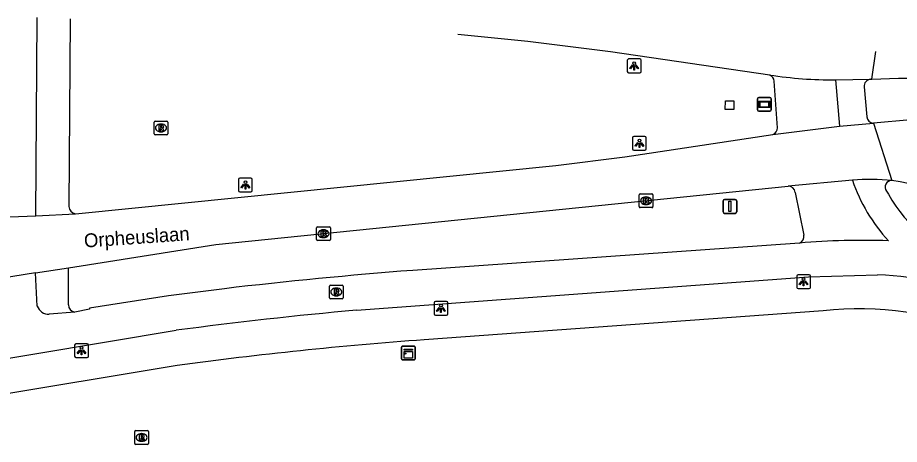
# Model space of a CAD drawing. Extents: x 161761 to 162722, y 384793 to 385405.
# Drawn here: x 161913.2 to 161977.1, y 385354.7 to 385385.6 of the extents above; entities that cross this region are included whole.
import ezdxf

# ---------------------------------------------------------------- set-up
doc = ezdxf.new("R2010")
doc.units = 0
for name, color, linetype in [('IMGEO_Berm_groen', 7, 'Continuous'), ('IMGEO_Fietspad_gesloten', 7, 'Continuous'), ('IMGEO_Kast', 7, 'Continuous'), ('IMGEO_Kolk', 7, 'Continuous'), ('IMGEO_Lichtpunt', 7, 'Continuous'), ('IMGEO_Openbare_ruimte_label', 7, 'Continuous'), ('IMGEO_Rijbaan_lokaal_gesloten', 7, 'Continuous'), ('IMGEO_Rioolput', 7, 'Continuous'), ('IMGEO_Straatnaambord', 7, 'Continuous'), ('IMGEO_Verkeersbordpaal', 7, 'Continuous'), ('IMGEO_Voetpad_open', 7, 'Continuous')]:
    doc.layers.add(name, color=color, linetype=linetype)

msp = doc.modelspace()

# ---------------------------------------------------------------- linework, layer by layer
at = {"layer": 'IMGEO_Berm_groen'}
msp.add_lwpolyline([(161964.504, 385379.586), (161965.1, 385379.595), (161965.105, 385378.974), (161964.466, 385378.952), (161964.504, 385379.586)], dxfattribs=at)
at = {"layer": 'IMGEO_Fietspad_gesloten'}
for points in [[(161914.544, 385371.27), (161914.64, 385385.619)], [(161972.454, 385381.101), (161972.759, 385377.761)], [(161974.546, 385380.611), (161974.742, 385378.438)], [(161976.151, 385373.042), (161976.299, 385372.83)], [(161969.866, 385369.286), (161941.846, 385367.307)], [(161914.653, 385364.708), (161914.537, 385367.119)], [(161937.781, 385364.42), (161970.497, 385366.829), (161975.511, 385366.99)], [(161928.204, 385365.982), (161924.166, 385365.467), (161918.434, 385364.558), (161918.442, 385364.486), (161917.367, 385364.291)], [(161917.367, 385364.291), (161915.514, 385364.129)], [(161909.275, 385360.387), (161924.722, 385362.965)]]:
    msp.add_lwpolyline(points, dxfattribs=at)
for centre, radius, start, end in [((161975.027, 385380.669), 0.484, 94.94392, 186.83642), ((161975.206, 385378.438), 0.464, 180.04152, 269.58683), ((161985.393, 385377.833), 12.367, 198.83171, 222.65699), ((161976.532, 385373.339), 0.483, 87.56385, 217.90438), ((161984.403, 385377.16), 9.188, 208.11884, 257.97269), ((161974.487, 385315.26), 54.223, 88.0859, 94.88867), ((161968.474, 385022.259), 346.074, 94.41287, 96.68221), ((161974.467, 385343.268), 23.745, 65.72803, 87.48046), ((161915.506, 385365.047), 0.918, 201.65335, 270.50705), ((161964.956, 385061.189), 304.447, 95.121, 97.59406)]:
    msp.add_arc(centre, radius, start, end, dxfattribs=at)
at = {"layer": 'IMGEO_Kast'}
for p, q in [((161941.029, 385360.894), (161941.029, 385361.735)), ((161941.029, 385361.735), (161941.029, 385360.894)), ((161941.104, 385361.819), (161941.945, 385361.819)), ((161941.945, 385361.819), (161941.104, 385361.819)), ((161942.029, 385361.744), (161942.029, 385360.903)), ((161942.029, 385360.903), (161942.029, 385361.744)), ((161941.954, 385360.819), (161941.113, 385360.819)), ((161941.113, 385360.819), (161941.954, 385360.819))]:
    msp.add_line(p, q, dxfattribs=at)
for points in [[(161941.224, 385361.609), (161941.824, 385361.609), (161941.824, 385361.524), (161941.224, 385361.524), (161941.224, 385361.609)], [(161941.224, 385361.434), (161941.824, 385361.434), (161941.824, 385360.945), (161941.224, 385360.945), (161941.224, 385361.434)]]:
    msp.add_lwpolyline(points, dxfattribs=at)
msp.add_circle((161941.308, 385361.283), 0.0377, dxfattribs=at)
for centre, start, end in [((161941.107, 385361.741), 92.4484, 184.28452), ((161941.107, 385361.741), 92.4484, 184.28452), ((161941.951, 385361.741), 2.4484, 94.28452), ((161941.951, 385361.741), 2.4484, 94.28452), ((161941.107, 385360.897), 182.4484, 274.28452), ((161941.107, 385360.897), 182.4484, 274.28452), ((161941.951, 385360.897), 272.4484, 4.28452), ((161941.951, 385360.897), 272.4484, 4.28452)]:
    msp.add_arc(centre, 0.0779, start, end, dxfattribs=at)
at = {"layer": 'IMGEO_Kolk'}
for p, q in [((161958.244, 385371.926), (161958.244, 385372.778)), ((161958.319, 385372.852), (161959.171, 385372.852)), ((161959.245, 385372.778), (161959.245, 385371.926)), ((161958.732, 385372.632), (161958.757, 385372.632)), ((161959.171, 385371.852), (161958.319, 385371.852)), ((161958.755, 385372.072), (161958.73, 385372.072)), ((161934.882, 385369.539), (161934.882, 385370.391)), ((161934.957, 385370.465), (161935.809, 385370.465)), ((161935.37, 385370.245), (161935.395, 385370.245)), ((161935.883, 385370.391), (161935.883, 385369.539)), ((161935.393, 385369.685), (161935.368, 385369.685)), ((161935.809, 385369.465), (161934.957, 385369.465))]:
    msp.add_line(p, q, dxfattribs=at)
for points in [[(161958.244, 385371.926), (161958.244, 385372.778)], [(161958.319, 385372.852), (161959.171, 385372.852)], [(161959.245, 385372.778), (161959.245, 385371.926)], [(161958.565, 385372.552), (161958.688, 385372.552), (161958.688, 385372.401), (161958.818, 385372.552), (161958.982, 385372.552), (161958.836, 385372.401), (161958.989, 385372.152), (161958.837, 385372.152), (161958.752, 385372.316), (161958.688, 385372.249), (161958.688, 385372.152), (161958.565, 385372.152), (161958.565, 385372.552)], [(161959.171, 385371.852), (161958.319, 385371.852)], [(161934.882, 385369.539), (161934.882, 385370.391)], [(161934.957, 385370.465), (161935.809, 385370.465)], [(161935.883, 385370.391), (161935.883, 385369.539)], [(161935.203, 385370.165), (161935.326, 385370.165), (161935.326, 385370.014), (161935.456, 385370.165), (161935.62, 385370.165), (161935.474, 385370.014), (161935.627, 385369.765), (161935.475, 385369.765), (161935.39, 385369.929), (161935.326, 385369.862), (161935.326, 385369.765), (161935.203, 385369.765), (161935.203, 385370.165)], [(161935.809, 385369.465), (161934.957, 385369.465)]]:
    msp.add_lwpolyline(points, dxfattribs=at)
for centre, start, end in [((161958.321, 385372.776), 91.55205, 178.44795), ((161958.321, 385372.776), 91.55205, 178.44795), ((161959.169, 385372.776), 1.55205, 88.44795), ((161959.169, 385372.776), 1.55205, 88.44795), ((161958.321, 385371.928), 181.55205, 268.44795), ((161958.321, 385371.928), 181.55205, 268.44795), ((161959.169, 385371.928), 271.55205, 358.44795), ((161959.169, 385371.928), 271.55205, 358.44795), ((161934.959, 385370.389), 91.55205, 178.44795), ((161934.959, 385370.389), 91.55205, 178.44795), ((161935.807, 385370.389), 1.55205, 88.44795), ((161935.807, 385370.389), 1.55205, 88.44795), ((161934.959, 385369.541), 181.55205, 268.44795), ((161934.959, 385369.541), 181.55205, 268.44795), ((161935.807, 385369.541), 271.55205, 358.44795), ((161935.807, 385369.541), 271.55205, 358.44795)]:
    msp.add_arc(centre, 0.0765, start, end, dxfattribs=at)
for centre, major_axis, ratio, start_param, end_param in [((161958.731, 385372.352), (-0.387, 0.002), 0.722429, 4.712389, 7.853982), ((161958.756, 385372.352), (-0.39, 0.002), 0.717154, 1.570796, 4.712389), ((161935.369, 385369.965), (-0.387, 0.002), 0.722429, 4.712389, 7.853982), ((161935.394, 385369.965), (-0.39, 0.002), 0.717154, 1.570796, 4.712389)]:
    msp.add_ellipse(centre, major_axis=major_axis, ratio=ratio, start_param=start_param, end_param=end_param, dxfattribs=at)
at = {"layer": 'IMGEO_Lichtpunt'}
for p, q in [((161957.386, 385382.527), (161957.386, 385381.72)), ((161957.386, 385382.527), (161957.386, 385381.72)), ((161958.288, 385382.622), (161957.48, 385382.622)), ((161958.288, 385382.622), (161957.48, 385382.622)), ((161958.382, 385381.72), (161958.382, 385382.527)), ((161958.382, 385381.72), (161958.382, 385382.527)), ((161957.48, 385381.626), (161958.288, 385381.626)), ((161957.48, 385381.626), (161958.288, 385381.626)), ((161957.764, 385376.919), (161957.764, 385376.112)), ((161957.764, 385376.919), (161957.764, 385376.112)), ((161958.666, 385377.014), (161957.858, 385377.014)), ((161958.666, 385377.014), (161957.858, 385377.014)), ((161958.76, 385376.112), (161958.76, 385376.919)), ((161958.76, 385376.112), (161958.76, 385376.919)), ((161957.858, 385376.018), (161958.666, 385376.018)), ((161957.858, 385376.018), (161958.666, 385376.018)), ((161929.227, 385373.901), (161929.227, 385373.094)), ((161929.227, 385373.901), (161929.227, 385373.094)), ((161930.129, 385373.996), (161929.321, 385373.996)), ((161930.129, 385373.996), (161929.321, 385373.996)), ((161930.223, 385373.094), (161930.223, 385373.901)), ((161930.223, 385373.094), (161930.223, 385373.901)), ((161929.321, 385373), (161930.129, 385373)), ((161929.321, 385373), (161930.129, 385373)), ((161969.653, 385366.884), (161969.653, 385366.077)), ((161969.653, 385366.884), (161969.653, 385366.077)), ((161970.555, 385366.979), (161969.747, 385366.979)), ((161970.555, 385366.979), (161969.747, 385366.979)), ((161970.649, 385366.077), (161970.649, 385366.884)), ((161970.649, 385366.077), (161970.649, 385366.884)), ((161969.747, 385365.983), (161970.555, 385365.983)), ((161969.747, 385365.983), (161970.555, 385365.983)), ((161943.392, 385364.958), (161943.392, 385364.151)), ((161943.392, 385364.958), (161943.392, 385364.151)), ((161944.294, 385365.053), (161943.486, 385365.053)), ((161944.294, 385365.053), (161943.486, 385365.053)), ((161944.388, 385364.151), (161944.388, 385364.958)), ((161944.388, 385364.151), (161944.388, 385364.958)), ((161943.486, 385364.057), (161944.294, 385364.057)), ((161943.486, 385364.057), (161944.294, 385364.057)), ((161918.265, 385361.993), (161917.457, 385361.993)), ((161918.265, 385361.993), (161917.457, 385361.993)), ((161917.363, 385361.898), (161917.363, 385361.091)), ((161917.363, 385361.898), (161917.363, 385361.091)), ((161918.359, 385361.091), (161918.359, 385361.898)), ((161918.359, 385361.091), (161918.359, 385361.898)), ((161917.457, 385360.997), (161918.265, 385360.997)), ((161917.457, 385360.997), (161918.265, 385360.997))]:
    msp.add_line(p, q, dxfattribs=at)
for points in [[(161957.76, 385382.191), (161957.799, 385382.163), (161957.611, 385381.901), (161957.573, 385381.928), (161957.76, 385382.191)], [(161957.862, 385382.143), (161957.909, 385382.143), (161957.909, 385381.821), (161957.862, 385381.821), (161957.862, 385382.143)], [(161957.972, 385382.163), (161958.01, 385382.19), (161958.197, 385381.928), (161958.158, 385381.9), (161957.972, 385382.163)], [(161958.138, 385376.583), (161958.177, 385376.555), (161957.989, 385376.293), (161957.951, 385376.32), (161958.138, 385376.583)], [(161958.24, 385376.535), (161958.287, 385376.535), (161958.287, 385376.213), (161958.24, 385376.213), (161958.24, 385376.535)], [(161958.35, 385376.555), (161958.388, 385376.582), (161958.575, 385376.32), (161958.536, 385376.292), (161958.35, 385376.555)], [(161929.601, 385373.565), (161929.64, 385373.537), (161929.452, 385373.275), (161929.414, 385373.302), (161929.601, 385373.565)], [(161929.703, 385373.517), (161929.75, 385373.517), (161929.75, 385373.195), (161929.703, 385373.195), (161929.703, 385373.517)], [(161929.813, 385373.537), (161929.851, 385373.564), (161930.038, 385373.302), (161929.999, 385373.274), (161929.813, 385373.537)], [(161970.027, 385366.548), (161970.066, 385366.52), (161969.878, 385366.258), (161969.84, 385366.285), (161970.027, 385366.548)], [(161970.129, 385366.5), (161970.176, 385366.5), (161970.176, 385366.178), (161970.129, 385366.178), (161970.129, 385366.5)], [(161970.239, 385366.52), (161970.277, 385366.547), (161970.464, 385366.285), (161970.425, 385366.257), (161970.239, 385366.52)], [(161943.766, 385364.622), (161943.805, 385364.594), (161943.617, 385364.332), (161943.579, 385364.359), (161943.766, 385364.622)], [(161943.868, 385364.574), (161943.915, 385364.574), (161943.915, 385364.252), (161943.868, 385364.252), (161943.868, 385364.574)], [(161943.978, 385364.594), (161944.016, 385364.621), (161944.203, 385364.359), (161944.164, 385364.331), (161943.978, 385364.594)], [(161917.737, 385361.562), (161917.776, 385361.534), (161917.588, 385361.272), (161917.55, 385361.299), (161917.737, 385361.562)], [(161917.839, 385361.514), (161917.886, 385361.514), (161917.886, 385361.192), (161917.839, 385361.192), (161917.839, 385361.514)], [(161917.949, 385361.534), (161917.987, 385361.561), (161918.174, 385361.299), (161918.135, 385361.271), (161917.949, 385361.534)]]:
    msp.add_lwpolyline(points, dxfattribs=at)
for centre in [(161957.885, 385382.325), (161958.263, 385376.717), (161929.726, 385373.699), (161970.152, 385366.682), (161943.891, 385364.756), (161917.862, 385361.696)]:
    msp.add_circle(centre, 0.0994, dxfattribs=at)
for centre, start, end in [((161957.48, 385382.527), 90, 180), ((161957.48, 385382.527), 90, 180), ((161958.288, 385382.527), 0, 90), ((161958.288, 385382.527), 0, 90), ((161957.48, 385381.72), 180, 270), ((161957.48, 385381.72), 180, 270), ((161958.288, 385381.72), 270, 0), ((161958.288, 385381.72), 270, 360), ((161957.858, 385376.919), 90, 180), ((161957.858, 385376.919), 90, 180), ((161958.666, 385376.919), 0, 90), ((161958.666, 385376.919), 0, 90), ((161957.858, 385376.112), 180, 270), ((161957.858, 385376.112), 180, 270), ((161958.666, 385376.112), 270, 0), ((161958.666, 385376.112), 270, 360), ((161929.321, 385373.901), 90, 180), ((161929.321, 385373.901), 90, 180), ((161930.129, 385373.901), 0, 90), ((161930.129, 385373.901), 0, 90), ((161929.321, 385373.094), 180, 270), ((161929.321, 385373.094), 180, 270), ((161930.129, 385373.094), 270, 0), ((161930.129, 385373.094), 270, 360), ((161969.747, 385366.884), 90, 180), ((161969.747, 385366.884), 90, 180), ((161970.555, 385366.884), 0, 90), ((161970.555, 385366.884), 0, 90), ((161969.747, 385366.077), 180, 270), ((161969.747, 385366.077), 180, 270), ((161970.555, 385366.077), 270, 0), ((161970.555, 385366.077), 270, 360), ((161943.486, 385364.958), 90, 180), ((161943.486, 385364.958), 90, 180), ((161944.294, 385364.958), 0, 90), ((161944.294, 385364.958), 0, 90), ((161943.486, 385364.151), 180, 270), ((161943.486, 385364.151), 180, 270), ((161944.294, 385364.151), 270, 0), ((161944.294, 385364.151), 270, 360), ((161917.457, 385361.898), 90, 180), ((161917.457, 385361.898), 90, 180), ((161918.265, 385361.898), 0, 90), ((161918.265, 385361.898), 0, 90), ((161917.457, 385361.091), 180, 270), ((161917.457, 385361.091), 180, 270), ((161918.265, 385361.091), 270, 0), ((161918.265, 385361.091), 270, 360)]:
    msp.add_arc(centre, 0.0946, start, end, dxfattribs=at)
at = {"layer": 'IMGEO_Rijbaan_lokaal_gesloten'}
for points in [[(161967.708, 385381.461), (161956.161, 385383.144), (161950.192, 385383.892), (161945.103, 385384.393)], [(161975.099, 385381.155), (161975.392, 385383.175)], [(161972.454, 385381.101), (161974.985, 385381.151)], [(161974.985, 385381.151), (161975.099, 385381.155)], [(161975.099, 385381.155), (161977.036, 385381.228), (161977.622, 385381.235)], [(161972.759, 385377.761), (161975.203, 385377.974)], [(161977.887, 385378.221), (161975.203, 385377.974)], [(161975.203, 385377.974), (161976.553, 385373.822)], [(161967.929, 385377.148), (161972.759, 385377.761)], [(161917.416, 385371.401), (161952.219, 385374.897), (161957.216, 385375.545), (161967.929, 385377.148)], [(161916.923, 385367.494), (161927.597, 385369.17), (161969.028, 385373.402)], [(161973.688, 385373.841), (161969.028, 385373.402)], [(161911.4, 385371.127), (161914.544, 385371.27)], [(161914.544, 385371.27), (161917.416, 385371.401)], [(161914.537, 385367.119), (161912.002, 385366.721), (161911.851, 385366.698)], [(161914.537, 385367.119), (161916.923, 385367.494)]]:
    msp.add_lwpolyline(points, dxfattribs=at)
for centre, radius, start, end in [((161972.504, 385413.223), 32.122, 261.4135, 269.91096), ((161975.002, 385356.017), 17.873, 85.02278, 94.21729), ((161974.637, 385360.427), 13.531, 42.06056, 81.86032)]:
    msp.add_arc(centre, radius, start, end, dxfattribs=at)
at = {"layer": 'IMGEO_Rioolput'}
for p, q in [((161923.114, 385377.199), (161923.114, 385378.051)), ((161923.189, 385378.125), (161924.041, 385378.125)), ((161923.602, 385377.905), (161923.627, 385377.905)), ((161924.115, 385378.051), (161924.115, 385377.199)), ((161923.625, 385377.345), (161923.6, 385377.345)), ((161924.041, 385377.125), (161923.189, 385377.125)), ((161935.812, 385365.317), (161935.812, 385366.169)), ((161935.887, 385366.243), (161936.739, 385366.243)), ((161936.3, 385366.023), (161936.325, 385366.023)), ((161936.813, 385366.169), (161936.813, 385365.317)), ((161936.739, 385365.243), (161935.887, 385365.243)), ((161936.323, 385365.463), (161936.298, 385365.463)), ((161921.709, 385354.776), (161921.709, 385355.628)), ((161921.784, 385355.702), (161922.636, 385355.702)), ((161922.71, 385355.628), (161922.71, 385354.776)), ((161922.22, 385354.922), (161922.195, 385354.922)), ((161922.197, 385355.482), (161922.222, 385355.482)), ((161922.636, 385354.702), (161921.784, 385354.702))]:
    msp.add_line(p, q, dxfattribs=at)
for points in [[(161923.114, 385377.199), (161923.114, 385378.051)], [(161923.189, 385378.125), (161924.041, 385378.125)], [(161924.115, 385378.051), (161924.115, 385377.199)], [(161923.703, 385377.823), (161923.451, 385377.825), (161923.451, 385377.425)], [(161923.451, 385377.425), (161923.575, 385377.425), (161923.575, 385377.587), (161923.586, 385377.587)], [(161923.629, 385377.744), (161923.575, 385377.744), (161923.575, 385377.663)], [(161923.575, 385377.663), (161923.627, 385377.663)], [(161923.633, 385377.558), (161923.704, 385377.425), (161923.844, 385377.425), (161923.779, 385377.551)], [(161924.041, 385377.125), (161923.189, 385377.125)], [(161935.812, 385365.317), (161935.812, 385366.169)], [(161935.887, 385366.243), (161936.739, 385366.243)], [(161936.401, 385365.941), (161936.149, 385365.943), (161936.149, 385365.543)], [(161936.327, 385365.862), (161936.273, 385365.862), (161936.273, 385365.781)], [(161936.273, 385365.781), (161936.325, 385365.781)], [(161936.813, 385366.169), (161936.813, 385365.317)], [(161936.739, 385365.243), (161935.887, 385365.243)], [(161936.149, 385365.543), (161936.273, 385365.543), (161936.273, 385365.705), (161936.284, 385365.705)], [(161936.331, 385365.676), (161936.402, 385365.543), (161936.542, 385365.543), (161936.477, 385365.669)], [(161921.709, 385354.776), (161921.709, 385355.628)], [(161921.784, 385355.702), (161922.636, 385355.702)], [(161922.71, 385355.628), (161922.71, 385354.776)], [(161922.298, 385355.4), (161922.046, 385355.402), (161922.046, 385355.002)], [(161922.046, 385355.002), (161922.17, 385355.002), (161922.17, 385355.164), (161922.181, 385355.164)], [(161922.224, 385355.321), (161922.17, 385355.321), (161922.17, 385355.24)], [(161922.17, 385355.24), (161922.222, 385355.24)], [(161922.228, 385355.135), (161922.299, 385355.002), (161922.439, 385355.002), (161922.374, 385355.128)], [(161922.636, 385354.702), (161921.784, 385354.702)]]:
    msp.add_lwpolyline(points, dxfattribs=at)
for centre, radius, start, end in [((161923.191, 385378.049), 0.0765, 91.55205, 178.44795), ((161923.191, 385378.049), 0.0765, 91.55205, 178.44795), ((161924.039, 385378.049), 0.0765, 1.55205, 88.44795), ((161924.039, 385378.049), 0.0765, 1.55205, 88.44795), ((161923.585, 385377.534), 0.0533, 26.02933, 88.69889), ((161923.611, 385377.852), 0.19, 274.7715, 282.96867), ((161923.635, 385377.648), 0.0964, 77.00612, 93.18647), ((161923.649, 385377.705), 0.0378, 276.66336, 79.67722), ((161923.702, 385377.713), 0.109, 350.36119, 89.41601), ((161923.7, 385377.713), 0.112, 277.58423, 350.98172), ((161923.684, 385377.498), 0.108, 29.51342, 73.79051), ((161923.191, 385377.201), 0.0765, 181.55205, 268.44795), ((161923.191, 385377.201), 0.0765, 181.55205, 268.44795), ((161924.039, 385377.201), 0.0765, 271.55205, 358.44795), ((161924.039, 385377.201), 0.0765, 271.55205, 358.44795), ((161935.889, 385366.167), 0.0765, 91.55205, 178.44795), ((161935.889, 385366.167), 0.0765, 91.55205, 178.44795), ((161936.309, 385365.97), 0.19, 274.7715, 282.96867), ((161936.333, 385365.766), 0.0964, 77.00612, 93.18647), ((161936.347, 385365.823), 0.0378, 276.66336, 79.67722), ((161936.4, 385365.831), 0.109, 350.36119, 89.41601), ((161936.398, 385365.831), 0.112, 277.58423, 350.98172), ((161936.737, 385366.167), 0.0765, 1.55205, 88.44795), ((161936.737, 385366.167), 0.0765, 1.55205, 88.44795), ((161935.889, 385365.319), 0.0765, 181.55205, 268.44795), ((161935.889, 385365.319), 0.0765, 181.55205, 268.44795), ((161936.283, 385365.652), 0.0533, 26.02933, 88.69889), ((161936.382, 385365.616), 0.108, 29.51342, 73.79051), ((161936.737, 385365.319), 0.0765, 271.55205, 358.44795), ((161936.737, 385365.319), 0.0765, 271.55205, 358.44795), ((161921.786, 385355.626), 0.0765, 91.55205, 178.44795), ((161921.786, 385355.626), 0.0765, 91.55205, 178.44795), ((161922.634, 385355.626), 0.0765, 1.55205, 88.44795), ((161922.634, 385355.626), 0.0765, 1.55205, 88.44795), ((161922.18, 385355.111), 0.0533, 26.02933, 88.69889), ((161922.206, 385355.429), 0.19, 274.7715, 282.96867), ((161922.23, 385355.225), 0.0964, 77.00612, 93.18647), ((161922.244, 385355.282), 0.0378, 276.66336, 79.67722), ((161922.297, 385355.29), 0.109, 350.36119, 89.41601), ((161922.295, 385355.29), 0.112, 277.58423, 350.98172), ((161922.279, 385355.075), 0.108, 29.51342, 73.79051), ((161921.786, 385354.778), 0.0765, 181.55205, 268.44795), ((161921.786, 385354.778), 0.0765, 181.55205, 268.44795), ((161922.634, 385354.778), 0.0765, 271.55205, 358.44795), ((161922.634, 385354.778), 0.0765, 271.55205, 358.44795)]:
    msp.add_arc(centre, radius, start, end, dxfattribs=at)
for centre, major_axis, ratio, start_param, end_param in [((161923.601, 385377.625), (-0.387, 0.002), 0.722429, 4.712389, 7.853982), ((161923.626, 385377.625), (-0.39, 0.002), 0.717154, 1.570796, 4.712389), ((161936.299, 385365.743), (-0.387, 0.002), 0.722429, 4.712389, 7.853982), ((161936.324, 385365.743), (-0.39, 0.002), 0.717154, 1.570796, 4.712389), ((161922.196, 385355.202), (-0.387, 0.002), 0.722429, 4.712389, 7.853982), ((161922.221, 385355.202), (-0.39, 0.002), 0.717154, 1.570796, 4.712389)]:
    msp.add_ellipse(centre, major_axis=major_axis, ratio=ratio, start_param=start_param, end_param=end_param, dxfattribs=at)
at = {"layer": 'IMGEO_Straatnaambord'}
for p, q in [((161966.909, 385379.833), (161967.699, 385379.833)), ((161967.699, 385379.833), (161966.909, 385379.833)), ((161966.809, 385378.933), (161966.809, 385379.733)), ((161966.809, 385379.733), (161966.809, 385378.933)), ((161967.799, 385379.733), (161967.799, 385378.933)), ((161967.799, 385378.933), (161967.799, 385379.733)), ((161967.699, 385378.833), (161966.909, 385378.833)), ((161966.909, 385378.833), (161967.699, 385378.833))]:
    msp.add_line(p, q, dxfattribs=at)
for points in [[(161966.91, 385379.565), (161967.698, 385379.565), (161967.698, 385379.101), (161966.91, 385379.101), (161966.91, 385379.565)], [(161966.975, 385379.5), (161966.975, 385379.166), (161967.633, 385379.166), (161967.633, 385379.5), (161966.975, 385379.5)]]:
    msp.add_lwpolyline(points, dxfattribs=at)
for centre, start, end in [((161966.909, 385379.733), 90, 180), ((161966.909, 385379.733), 90, 180), ((161967.699, 385379.733), 0, 90), ((161967.699, 385379.733), 360, 90), ((161966.909, 385378.933), 180, 270), ((161966.909, 385378.933), 180, 270), ((161967.699, 385378.933), 270, 0), ((161967.699, 385378.933), 270, 0)]:
    msp.add_arc(centre, 0.1, start, end, dxfattribs=at)
at = {"layer": 'IMGEO_Verkeersbordpaal'}
for p, q in [((161964.317, 385371.54), (161964.317, 385372.34)), ((161964.317, 385372.34), (161964.317, 385371.54)), ((161964.417, 385372.44), (161965.207, 385372.44)), ((161965.207, 385372.44), (161964.417, 385372.44)), ((161965.307, 385372.34), (161965.307, 385371.54)), ((161965.307, 385371.54), (161965.307, 385372.34)), ((161965.207, 385371.44), (161964.417, 385371.44)), ((161964.417, 385371.44), (161965.207, 385371.44))]:
    msp.add_line(p, q, dxfattribs=at)
msp.add_lwpolyline([(161964.737, 385372.315), (161964.887, 385372.315), (161964.887, 385371.565), (161964.737, 385371.565), (161964.737, 385372.315)], dxfattribs=at)
for centre, start, end in [((161964.417, 385372.34), 90, 180), ((161964.417, 385372.34), 90, 180), ((161965.207, 385372.34), 0, 90), ((161965.207, 385372.34), 360, 90), ((161964.417, 385371.54), 180, 270), ((161964.417, 385371.54), 180, 270), ((161965.207, 385371.54), 270, 0), ((161965.207, 385371.54), 270, 0)]:
    msp.add_arc(centre, 0.1, start, end, dxfattribs=at)
at = {"layer": 'IMGEO_Voetpad_open'}
for points in [[(161917.049, 385385.522), (161916.952, 385371.936)], [(161968.253, 385377.641), (161968.024, 385381.02)], [(161969.539, 385372.958), (161970.163, 385369.853)], [(161916.916, 385364.811), (161916.923, 385367.494)], [(161971.573, 385364.366), (161942.672, 385362.279)], [(161924.792, 385360.416), (161910.683, 385358.067)]]:
    msp.add_lwpolyline(points, dxfattribs=at)
for centre, radius, start, end in [((161967.467, 385380.954), 0.561, 6.7151, 64.53213), ((161967.777, 385377.601), 0.477, 288.51413, 4.85997), ((161969.053, 385372.915), 0.488, 5.1004, 92.92586), ((161917.53, 385371.969), 0.579, 183.2499, 258.61963), ((161969.646, 385369.762), 0.525, 294.7652, 9.94285), ((161917.428, 385364.799), 0.512, 178.69969, 263.17101), ((161974.266, 385343.076), 21.459, 65.15824, 97.20826), ((161963.563, 385075.051), 287.987, 94.15989, 97.73701)]:
    msp.add_arc(centre, radius, start, end, dxfattribs=at)

# ---------------------------------------------------------------- texts
at = {"layer": 'IMGEO_Openbare_ruimte_label'}
msp.add_text('Orpheuslaan', height=1, rotation=4.01217, dxfattribs=at).set_placement((161918.075, 385368.955))

doc.saveas('drawing.dxf')
